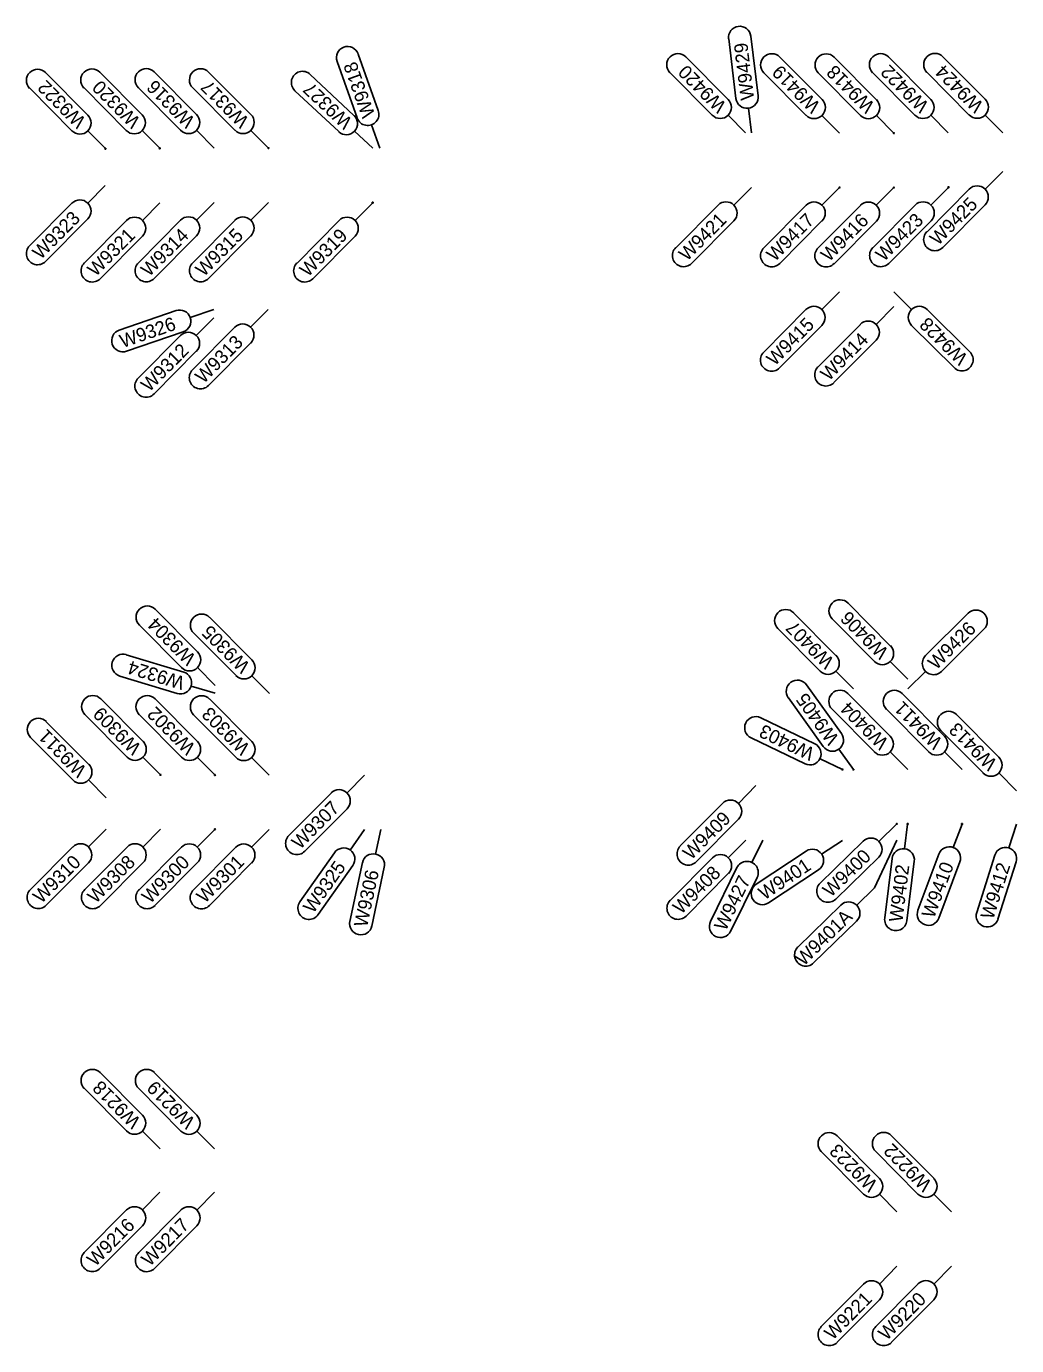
# Model space of a CAD drawing. Extents: x 12479652 to 12487250, y 9842710 to 9846560.
# Drawn here: x 12483660 to 12483751.1, y 9844143 to 9844264.3 of the extents above; entities that cross this region are included whole.
import ezdxf

# ---------------------------------------------------------------- set-up
doc = ezdxf.new("R2010")
doc.units = 0
for name, color, linetype in [('_CIVIL_CONSTRUCTION', 7, 'Continuous'), ('Default', 7, 'Continuous'), ('TextAlignmentLrg', 7, 'Continuous')]:
    doc.layers.add(name, color=color, linetype=linetype)

msp = doc.modelspace()

# ---------------------------------------------------------------- linework, layer by layer
at = {"layer": '_CIVIL_CONSTRUCTION'}
msp.add_line((12483738.04, 9844185.05), (12483740.08, 9844189.43), dxfattribs=at)
at = {"layer": 'Default'}
for p, q in [((12483724.62, 9844263.12), (12483725.29, 9844257.64)), ((12483727.33, 9844257.9), (12483726.65, 9844263.37)), ((12483692.39, 9844256.54), (12483690.53, 9844261.73)), ((12483724.56, 9844257.55), (12483720.67, 9844261.47)), ((12483733.21, 9844257.54), (12483729.32, 9844261.45)), ((12483738.21, 9844257.53), (12483734.32, 9844261.45)), ((12483743.21, 9844257.55), (12483739.32, 9844261.46)), ((12483748.21, 9844257.57), (12483744.32, 9844261.48)), ((12483665.68, 9844256.11), (12483661.79, 9844260.03)), ((12483670.68, 9844256.14), (12483666.79, 9844260.05)), ((12483675.68, 9844256.17), (12483671.79, 9844260.08)), ((12483680.68, 9844256.16), (12483676.79, 9844260.07)), ((12483690.16, 9844256.09), (12483686.14, 9844259.86)), ((12483688.6, 9844261.04), (12483690.46, 9844255.85)), ((12483719.22, 9844260.02), (12483723.11, 9844256.11)), ((12483727.86, 9844260.01), (12483731.75, 9844256.09)), ((12483732.86, 9844260), (12483736.75, 9844256.09)), ((12483737.86, 9844260.02), (12483741.75, 9844256.11)), ((12483742.86, 9844260.04), (12483746.75, 9844256.12)), ((12483660.34, 9844258.58), (12483664.22, 9844254.67)), ((12483665.34, 9844258.61), (12483669.22, 9844254.69)), ((12483670.34, 9844258.63), (12483674.22, 9844254.72)), ((12483675.34, 9844258.63), (12483679.22, 9844254.71)), ((12483684.73, 9844258.36), (12483688.76, 9844254.59)), ((12483726.72, 9844254.47), (12483726.44, 9844256.75)), ((12483692.54, 9844253.06), (12483691.77, 9844255.23)), ((12483726.18, 9844254.47), (12483724.56, 9844256.1)), ((12483734.82, 9844254.46), (12483733.2, 9844256.09)), ((12483739.82, 9844254.45), (12483738.2, 9844256.08)), ((12483744.82, 9844254.47), (12483743.2, 9844256.1)), ((12483749.82, 9844254.49), (12483748.2, 9844256.12)), ((12483667.3, 9844253.03), (12483665.68, 9844254.66)), ((12483672.3, 9844253.06), (12483670.68, 9844254.69)), ((12483677.3, 9844253.08), (12483675.68, 9844254.72)), ((12483682.3, 9844253.08), (12483680.68, 9844254.71)), ((12483691.89, 9844253.06), (12483690.21, 9844254.64)), ((12483749.82, 9844250.94), (12483748.2, 9844249.31)), ((12483667.29, 9844249.65), (12483665.67, 9844248.02)), ((12483726.71, 9844249.47), (12483725.09, 9844247.84)), ((12483734.82, 9844249.46), (12483733.19, 9844247.83)), ((12483739.82, 9844249.45), (12483738.19, 9844247.82)), ((12483742.86, 9844245.39), (12483746.75, 9844249.3)), ((12483744.84, 9844249.47), (12483743.22, 9844247.84)), ((12483660.33, 9844244.1), (12483664.22, 9844248.01)), ((12483672.32, 9844248.06), (12483670.7, 9844246.43)), ((12483677.29, 9844248.08), (12483675.67, 9844246.45)), ((12483682.29, 9844248.08), (12483680.67, 9844246.45)), ((12483691.88, 9844248.06), (12483690.26, 9844246.43)), ((12483719.75, 9844243.92), (12483723.64, 9844247.83)), ((12483727.85, 9844243.91), (12483731.74, 9844247.82)), ((12483732.85, 9844243.9), (12483736.74, 9844247.81)), ((12483737.88, 9844243.92), (12483741.77, 9844247.83)), ((12483748.2, 9844247.86), (12483744.31, 9844243.94)), ((12483665.67, 9844246.57), (12483661.79, 9844242.65)), ((12483665.36, 9844242.51), (12483669.25, 9844246.42)), ((12483670.33, 9844242.54), (12483674.22, 9844246.45)), ((12483675.33, 9844242.53), (12483679.22, 9844246.44)), ((12483684.92, 9844242.51), (12483688.81, 9844246.43)), ((12483725.1, 9844246.39), (12483721.21, 9844242.47)), ((12483733.2, 9844246.38), (12483729.31, 9844242.46)), ((12483738.2, 9844246.37), (12483734.31, 9844242.45)), ((12483743.23, 9844246.39), (12483739.34, 9844242.47)), ((12483670.71, 9844244.98), (12483666.82, 9844241.06)), ((12483675.67, 9844245), (12483671.78, 9844241.09)), ((12483680.67, 9844245), (12483676.78, 9844241.08)), ((12483690.26, 9844244.98), (12483686.37, 9844241.07)), ((12483734.8, 9844239.86), (12483733.18, 9844238.23)), ((12483739.8, 9844239.86), (12483741.43, 9844238.23)), ((12483668.58, 9844236.34), (12483673.8, 9844238.13)), ((12483677.27, 9844238.25), (12483675.1, 9844237.5)), ((12483682.27, 9844238.24), (12483680.65, 9844236.61)), ((12483727.84, 9844234.31), (12483731.73, 9844238.23)), ((12483739.8, 9844238.5), (12483738.18, 9844236.87)), ((12483742.88, 9844238.24), (12483746.8, 9844234.35)), ((12483677.27, 9844237.47), (12483675.65, 9844235.84)), ((12483732.84, 9844232.96), (12483736.73, 9844236.87)), ((12483674.46, 9844236.19), (12483669.25, 9844234.4)), ((12483670.31, 9844231.92), (12483674.2, 9844235.84)), ((12483675.31, 9844232.69), (12483679.2, 9844236.6)), ((12483733.18, 9844236.78), (12483729.29, 9844232.87)), ((12483745.35, 9844232.89), (12483741.44, 9844236.78)), ((12483675.66, 9844234.39), (12483671.77, 9844230.48)), ((12483680.66, 9844235.16), (12483676.77, 9844231.25)), ((12483738.18, 9844235.42), (12483734.29, 9844231.51)), ((12483675.77, 9844206.75), (12483671.88, 9844210.67)), ((12483734.48, 9844206.43), (12483730.59, 9844210.34)), ((12483739.48, 9844207.32), (12483735.6, 9844211.24)), ((12483746.65, 9844210.3), (12483742.73, 9844206.41)), ((12483670.42, 9844209.22), (12483674.31, 9844205.31)), ((12483680.77, 9844206.02), (12483676.88, 9844209.93)), ((12483734.14, 9844209.79), (12483738.03, 9844205.88)), ((12483675.42, 9844208.48), (12483679.31, 9844204.57)), ((12483729.14, 9844208.9), (12483733.03, 9844204.98)), ((12483744.18, 9844204.95), (12483748.09, 9844208.84)), ((12483674.5, 9844204.89), (12483669.22, 9844206.49)), ((12483677.39, 9844203.67), (12483675.76, 9844205.3)), ((12483741.1, 9844204.24), (12483739.48, 9844205.87)), ((12483668.63, 9844204.53), (12483673.9, 9844202.93)), ((12483682.38, 9844202.93), (12483680.76, 9844204.56)), ((12483736.1, 9844203.35), (12483734.48, 9844204.98)), ((12483741.1, 9844203.34), (12483742.73, 9844204.96)), ((12483677.38, 9844202.94), (12483675.18, 9844203.61)), ((12483734.99, 9844199.23), (12483731.78, 9844203.72)), ((12483739.47, 9844199.01), (12483735.58, 9844202.92)), ((12483744.47, 9844199), (12483740.58, 9844202.91)), ((12483670.76, 9844198.52), (12483666.87, 9844202.43)), ((12483675.76, 9844198.51), (12483671.87, 9844202.42)), ((12483680.76, 9844198.5), (12483676.87, 9844202.42)), ((12483730.11, 9844202.53), (12483733.32, 9844198.04)), ((12483665.41, 9844200.98), (12483669.3, 9844197.07)), ((12483670.41, 9844200.98), (12483674.3, 9844197.06)), ((12483675.41, 9844200.97), (12483679.3, 9844197.06)), ((12483732.54, 9844198.3), (12483727.57, 9844200.69)), ((12483734.13, 9844201.47), (12483738.02, 9844197.56)), ((12483739.13, 9844201.47), (12483743.02, 9844197.55)), ((12483749.47, 9844197.07), (12483745.58, 9844200.98)), ((12483665.75, 9844196.42), (12483661.86, 9844200.33)), ((12483744.12, 9844199.53), (12483748.01, 9844195.62)), ((12483660.41, 9844198.88), (12483664.3, 9844194.97)), ((12483726.68, 9844198.84), (12483731.65, 9844196.45)), ((12483672.37, 9844195.44), (12483670.75, 9844197.07)), ((12483677.37, 9844195.43), (12483675.75, 9844197.06)), ((12483682.37, 9844195.42), (12483680.75, 9844197.05)), ((12483735.09, 9844195.93), (12483733.02, 9844196.93)), ((12483736.09, 9844195.93), (12483734.75, 9844197.8)), ((12483741.09, 9844195.92), (12483739.47, 9844197.56)), ((12483746.09, 9844195.92), (12483744.47, 9844197.55)), ((12483751.09, 9844193.98), (12483749.46, 9844195.62)), ((12483667.37, 9844193.34), (12483665.75, 9844194.97)), ((12483691.14, 9844195.41), (12483689.52, 9844193.78)), ((12483727.13, 9844194.45), (12483725.51, 9844192.81)), ((12483684.18, 9844189.86), (12483688.07, 9844193.77)), ((12483689.52, 9844192.33), (12483685.63, 9844188.41)), ((12483720.17, 9844188.9), (12483724.06, 9844192.81)), ((12483725.51, 9844191.36), (12483721.63, 9844187.45)), ((12483740.08, 9844190.93), (12483738.43, 9844189.32)), ((12483741.08, 9844190.92), (12483740.8, 9844188.64)), ((12483746.08, 9844190.92), (12483745.28, 9844188.76)), ((12483751.08, 9844190.91), (12483750.39, 9844188.72)), ((12483667.37, 9844190.44), (12483665.74, 9844188.81)), ((12483672.37, 9844190.44), (12483670.74, 9844188.8)), ((12483677.37, 9844190.43), (12483675.74, 9844188.8)), ((12483682.37, 9844190.42), (12483680.74, 9844188.79)), ((12483691.13, 9844190.41), (12483689.8, 9844188.53)), ((12483692.64, 9844190.41), (12483692.15, 9844188.16)), ((12483660.4, 9844184.9), (12483664.29, 9844188.81)), ((12483665.4, 9844184.89), (12483669.29, 9844188.8)), ((12483670.4, 9844184.88), (12483674.29, 9844188.79)), ((12483675.4, 9844184.87), (12483679.29, 9844188.79)), ((12483685.19, 9844183.77), (12483688.37, 9844188.28)), ((12483726.2, 9844189.45), (12483724.58, 9844187.82)), ((12483727.77, 9844189.44), (12483726.76, 9844187.38)), ((12483727.16, 9844185.38), (12483731.75, 9844188.43)), ((12483733.03, 9844185.49), (12483736.98, 9844189.34)), ((12483735.09, 9844189.42), (12483733.17, 9844188.14)), ((12483665.75, 9844187.36), (12483661.86, 9844183.45)), ((12483670.75, 9844187.35), (12483666.86, 9844183.44)), ((12483675.75, 9844187.35), (12483671.86, 9844183.43)), ((12483680.75, 9844187.34), (12483676.86, 9844183.43)), ((12483690.05, 9844187.1), (12483686.87, 9844182.59)), ((12483689.78, 9844181.97), (12483690.94, 9844187.37)), ((12483719.24, 9844183.9), (12483723.13, 9844187.81)), ((12483738.42, 9844187.87), (12483734.46, 9844184.02)), ((12483738.97, 9844182.28), (12483739.65, 9844187.75)), ((12483741.69, 9844187.5), (12483741.01, 9844182.02)), ((12483742.03, 9844182.99), (12483743.96, 9844188.16)), ((12483745.88, 9844187.44), (12483743.95, 9844182.27)), ((12483747.43, 9844182.79), (12483749.1, 9844188.05)), ((12483751.05, 9844187.43), (12483749.38, 9844182.17)), ((12483692.94, 9844186.94), (12483691.79, 9844181.54)), ((12483724.58, 9844186.36), (12483720.7, 9844182.45)), ((12483722.95, 9844181.96), (12483725.38, 9844186.91)), ((12483727.23, 9844186.01), (12483724.79, 9844181.05)), ((12483732.89, 9844186.72), (12483728.29, 9844183.67)), ((12483738.04, 9844185.05), (12483736.39, 9844183.44)), ((12483730.99, 9844179.61), (12483734.94, 9844183.46)), ((12483736.37, 9844181.99), (12483732.42, 9844178.14)), ((12483670.71, 9844164.15), (12483666.82, 9844168.06)), ((12483675.71, 9844164.14), (12483671.82, 9844168.05)), ((12483665.37, 9844166.61), (12483669.25, 9844162.7)), ((12483670.37, 9844166.6), (12483674.25, 9844162.69)), ((12483672.33, 9844161.06), (12483670.71, 9844162.69)), ((12483677.33, 9844161.06), (12483675.71, 9844162.69)), ((12483738.48, 9844158.33), (12483734.6, 9844162.25)), ((12483743.48, 9844158.34), (12483739.6, 9844162.25)), ((12483733.14, 9844160.8), (12483737.03, 9844156.89)), ((12483738.14, 9844160.8), (12483742.03, 9844156.89)), ((12483672.32, 9844157.06), (12483670.7, 9844155.43)), ((12483677.32, 9844157.06), (12483675.7, 9844155.42)), ((12483740.1, 9844155.25), (12483738.48, 9844156.88)), ((12483745.1, 9844155.25), (12483743.48, 9844156.89)), ((12483665.36, 9844151.51), (12483669.25, 9844155.43)), ((12483670.36, 9844151.51), (12483674.25, 9844155.42)), ((12483670.7, 9844153.98), (12483666.81, 9844150.07)), ((12483675.7, 9844153.97), (12483671.81, 9844150.06)), ((12483740.1, 9844150.25), (12483738.48, 9844148.62)), ((12483745.1, 9844150.25), (12483743.48, 9844148.62)), ((12483733.14, 9844144.7), (12483737.03, 9844148.62)), ((12483738.14, 9844144.71), (12483742.03, 9844148.62)), ((12483738.49, 9844147.17), (12483734.6, 9844143.26)), ((12483743.49, 9844147.17), (12483739.6, 9844143.26))]:
    msp.add_line(p, q, dxfattribs=at)
for centre, start, end in [((12483725.63, 9844263.25), 7.0658, 187.0658), ((12483689.57, 9844261.39), 19.665, 199.665), ((12483719.95, 9844260.74), 44.8253, 224.8253), ((12483728.59, 9844260.73), 44.8253, 224.8253), ((12483733.59, 9844260.72), 44.8253, 224.8253), ((12483738.59, 9844260.74), 44.8253, 224.8253), ((12483743.59, 9844260.76), 44.8253, 224.8253), ((12483661.06, 9844259.3), 44.8253, 224.8253), ((12483666.06, 9844259.33), 44.8253, 224.8253), ((12483671.06, 9844259.36), 44.8253, 224.8253), ((12483676.06, 9844259.35), 44.8253, 224.8253), ((12483685.43, 9844259.11), 46.8471, 226.8471), ((12483723.84, 9844256.83), 224.8253, 44.8253), ((12483726.31, 9844257.77), 187.0658, 7.0658), ((12483732.48, 9844256.82), 224.8253, 44.8253), ((12483737.48, 9844256.81), 224.8253, 44.8253), ((12483742.48, 9844256.83), 224.8253, 44.8253), ((12483747.48, 9844256.85), 224.8253, 44.8253), ((12483691.42, 9844256.19), 199.665, 19.665), ((12483664.95, 9844255.39), 224.8253, 44.8253), ((12483669.95, 9844255.42), 224.8253, 44.8253), ((12483674.95, 9844255.44), 224.8253, 44.8253), ((12483679.95, 9844255.44), 224.8253, 44.8253), ((12483689.46, 9844255.34), 226.8471, 46.8471), ((12483747.47, 9844248.58), 315.1702, 135.1702), ((12483664.95, 9844247.29), 315.1702, 135.1702), ((12483724.37, 9844247.11), 315.1702, 135.1702), ((12483732.47, 9844247.1), 315.1702, 135.1702), ((12483737.47, 9844247.09), 315.1702, 135.1702), ((12483742.5, 9844247.11), 315.1702, 135.1702), ((12483669.98, 9844245.7), 315.1702, 135.1702), ((12483674.94, 9844245.73), 315.1702, 135.1702), ((12483679.94, 9844245.72), 315.1702, 135.1702), ((12483689.53, 9844245.7), 315.1702, 135.1702), ((12483743.58, 9844244.67), 135.1702, 315.1702), ((12483661.06, 9844243.38), 135.1702, 315.1702), ((12483720.48, 9844243.2), 135.1702, 315.1702), ((12483728.58, 9844243.19), 135.1702, 315.1702), ((12483733.58, 9844243.18), 135.1702, 315.1702), ((12483738.61, 9844243.2), 135.1702, 315.1702), ((12483666.09, 9844241.79), 135.1702, 315.1702), ((12483671.06, 9844241.81), 135.1702, 315.1702), ((12483676.06, 9844241.81), 135.1702, 315.1702), ((12483685.64, 9844241.79), 135.1702, 315.1702), ((12483674.13, 9844237.16), 289.0233, 109.0233), ((12483732.46, 9844237.5), 315.1702, 135.1702), ((12483742.16, 9844237.51), 45.1702, 225.1702), ((12483679.93, 9844235.88), 315.1702, 135.1702), ((12483737.45, 9844236.14), 315.1702, 135.1702), ((12483668.91, 9844235.37), 109.0233, 289.0233), ((12483674.93, 9844235.11), 315.1702, 135.1702), ((12483728.57, 9844233.59), 135.1702, 315.1702), ((12483746.07, 9844233.62), 225.1702, 45.1702), ((12483676.04, 9844231.97), 135.1702, 315.1702), ((12483733.56, 9844232.23), 135.1702, 315.1702), ((12483671.04, 9844231.2), 135.1702, 315.1702), ((12483734.87, 9844210.51), 44.8253, 224.8253), ((12483671.15, 9844209.94), 44.8253, 224.8253), ((12483676.15, 9844209.2), 44.8253, 224.8253), ((12483729.87, 9844209.62), 44.8253, 224.8253), ((12483747.37, 9844209.57), 314.8253, 134.8253), ((12483668.92, 9844205.51), 73.1071, 253.1071), ((12483675.04, 9844206.03), 224.8253, 44.8253), ((12483738.76, 9844206.6), 224.8253, 44.8253), ((12483680.04, 9844205.29), 224.8253, 44.8253), ((12483733.76, 9844205.71), 224.8253, 44.8253), ((12483743.46, 9844205.68), 134.8253, 314.8253), ((12483674.2, 9844203.91), 253.1071, 73.1071), ((12483730.94, 9844203.12), 35.5978, 215.5978), ((12483734.86, 9844202.2), 44.8253, 224.8253), ((12483739.86, 9844202.19), 44.8253, 224.8253), ((12483666.14, 9844201.71), 44.8253, 224.8253), ((12483671.14, 9844201.7), 44.8253, 224.8253), ((12483676.14, 9844201.69), 44.8253, 224.8253), ((12483661.14, 9844199.61), 44.8253, 224.8253), ((12483727.12, 9844199.77), 64.3063, 244.3063), ((12483744.85, 9844200.26), 44.8253, 224.8253), ((12483734.15, 9844198.64), 215.5978, 35.5978), ((12483670.03, 9844197.8), 224.8253, 44.8253), ((12483675.03, 9844197.79), 224.8253, 44.8253), ((12483680.03, 9844197.78), 224.8253, 44.8253), ((12483732.09, 9844197.38), 244.3063, 64.3063), ((12483738.74, 9844198.28), 224.8253, 44.8253), ((12483743.74, 9844198.28), 224.8253, 44.8253), ((12483748.74, 9844196.34), 224.8253, 44.8253), ((12483665.03, 9844195.7), 224.8253, 44.8253), ((12483688.79, 9844193.05), 315.1702, 135.1702), ((12483724.79, 9844192.09), 315.1702, 135.1702), ((12483684.9, 9844189.14), 135.1702, 315.1702), ((12483737.7, 9844188.6), 314.2533, 134.2533), ((12483665.02, 9844188.08), 315.1702, 135.1702), ((12483670.02, 9844188.08), 315.1702, 135.1702), ((12483675.02, 9844188.07), 315.1702, 135.1702), ((12483680.02, 9844188.06), 315.1702, 135.1702), ((12483689.21, 9844187.69), 324.788, 144.788), ((12483720.9, 9844188.17), 135.1702, 315.1702), ((12483732.32, 9844187.58), 303.5694, 123.5694), ((12483740.67, 9844187.62), 352.9021, 172.9021), ((12483744.92, 9844187.8), 339.5552, 159.5552), ((12483750.08, 9844187.74), 342.3954, 162.3954), ((12483691.94, 9844187.15), 347.9405, 167.9405), ((12483723.86, 9844187.09), 315.1702, 135.1702), ((12483726.31, 9844186.46), 333.8437, 153.8437), ((12483661.13, 9844184.17), 135.1702, 315.1702), ((12483666.13, 9844184.16), 135.1702, 315.1702), ((12483671.13, 9844184.16), 135.1702, 315.1702), ((12483676.13, 9844184.15), 135.1702, 315.1702), ((12483727.72, 9844184.53), 123.5694, 303.5694), ((12483733.75, 9844184.75), 134.2533, 314.2533), ((12483686.03, 9844183.18), 144.788, 324.788), ((12483719.97, 9844183.18), 135.1702, 315.1702), ((12483735.66, 9844182.73), 314.2533, 134.2533), ((12483739.99, 9844182.15), 172.9021, 352.9021), ((12483742.99, 9844182.63), 159.5552, 339.5552), ((12483748.41, 9844182.48), 162.3954, 342.3954), ((12483690.79, 9844181.76), 167.9405, 347.9405), ((12483723.87, 9844181.51), 153.8437, 333.8437), ((12483731.71, 9844178.88), 134.2533, 314.2533), ((12483666.09, 9844167.33), 44.8253, 224.8253), ((12483671.09, 9844167.33), 44.8253, 224.8253), ((12483669.98, 9844163.42), 224.8253, 44.8253), ((12483674.98, 9844163.41), 224.8253, 44.8253), ((12483733.87, 9844161.52), 44.8253, 224.8253), ((12483738.87, 9844161.53), 44.8253, 224.8253), ((12483737.76, 9844157.61), 224.8253, 44.8253), ((12483742.76, 9844157.61), 224.8253, 44.8253), ((12483669.98, 9844154.7), 315.1702, 135.1702), ((12483674.98, 9844154.7), 315.1702, 135.1702), ((12483666.09, 9844150.79), 135.1702, 315.1702), ((12483671.09, 9844150.78), 135.1702, 315.1702), ((12483737.76, 9844147.89), 315.1702, 135.1702), ((12483742.76, 9844147.9), 315.1702, 135.1702), ((12483733.87, 9844143.98), 135.1702, 315.1702), ((12483738.87, 9844143.98), 135.1702, 315.1702)]:
    msp.add_arc(centre, 1.03, start, end, dxfattribs=at)
at = {"layer": 'TextAlignmentLrg'}
for centre in [(12483739.82, 9844254.45), (12483667.3, 9844253.03), (12483672.3, 9844253.06), (12483682.3, 9844253.08), (12483734.82, 9844249.46), (12483739.82, 9844249.45), (12483744.84, 9844249.47), (12483691.88, 9844248.06), (12483735.09, 9844195.93), (12483736.09, 9844195.93), (12483672.37, 9844195.44), (12483677.37, 9844195.43), (12483740.08, 9844190.93), (12483741.08, 9844190.92), (12483746.08, 9844190.92), (12483677.37, 9844190.43)]:
    msp.add_circle(centre, 0.05, dxfattribs=at)

# ---------------------------------------------------------------- texts
at = {"layer": 'Default'}
for s, rotation, p in [('W9429', 97.0658, (12483726.98, 9844257.57)), ('W9318', 109.665, (12483692.12, 9844256.14)), ('W9420', 134.8253, (12483724.49, 9844257.07)), ('W9419', 134.8253, (12483733.13, 9844257.06)), ('W9418', 134.8253, (12483738.13, 9844257.06)), ('W9422', 134.8253, (12483743.11, 9844257.09)), ('W9424', 134.8253, (12483748.14, 9844257.09)), ('W9322', 134.8253, (12483665.58, 9844255.66)), ('W9320', 134.8253, (12483670.6, 9844255.66)), ('W9316', 134.8253, (12483675.61, 9844255.69)), ('W9317', 134.8253, (12483680.59, 9844255.69)), ('W9327', 136.8471, (12483690.09, 9844255.62)), ('W9425', 45.1702, (12483743.87, 9844244.05)), ('W9323', 45.1702, (12483661.34, 9844242.76)), ('W9421', 45.1702, (12483720.79, 9844242.61)), ('W9417', 45.1702, (12483728.86, 9844242.57)), ('W9416', 45.1702, (12483733.85, 9844242.55)), ('W9423', 45.1702, (12483738.89, 9844242.58)), ('W9321', 45.1702, (12483666.4, 9844241.19)), ('W9314', 45.1702, (12483671.32, 9844241.18)), ('W9315', 45.1702, (12483676.34, 9844241.19)), ('W9319', 45.1702, (12483685.92, 9844241.16)), ('W9326', 19.0233, (12483668.88, 9844234.68)), ('W9415', 45.1702, (12483728.85, 9844232.98)), ('W9428', 135.1702, (12483746.7, 9844233.89)), ('W9313', 45.1702, (12483676.32, 9844231.35)), ('W9414', 45.1702, (12483733.83, 9844231.6)), ('W9312', 45.1702, (12483671.33, 9844230.59)), ('W9406', 134.8253, (12483739.41, 9844206.84)), ('W9304', 134.8253, (12483675.7, 9844206.27)), ('W9305', 134.8253, (12483680.68, 9844205.55)), ('W9407', 134.8253, (12483734.4, 9844205.96)), ('W9426', 44.8253, (12483743.7, 9844205.03)), ('W9324', 163.1071, (12483674.67, 9844204.43)), ('W9405', 125.5978, (12483734.83, 9844198.79)), ('W9302', 134.8253, (12483675.66, 9844198.05)), ('W9404', 134.8253, (12483739.4, 9844198.52)), ('W9411', 134.8253, (12483744.36, 9844198.56)), ('W9309', 134.8253, (12483670.68, 9844198.04)), ('W9303', 134.8253, (12483680.67, 9844198.03)), ('W9311', 134.8253, (12483665.64, 9844195.98)), ('W9403', 154.3063, (12483732.61, 9844197.83)), ('W9413', 134.8253, (12483749.39, 9844196.6)), ('W9307', 45.1702, (12483685.19, 9844188.52)), ('W9409', 45.1702, (12483721.17, 9844187.55)), ('W9400', 44.2533, (12483734.01, 9844184.12)), ('W9310', 45.1702, (12483661.4, 9844183.54)), ('W9308', 45.1702, (12483666.4, 9844183.54)), ('W9300', 45.1702, (12483671.4, 9844183.53)), ('W9301', 45.1702, (12483676.44, 9844183.56)), ('W9325', 54.788, (12483686.41, 9844182.62)), ('W9401', 33.5694, (12483727.9, 9844183.88)), ('W9402', 82.9021, (12483740.59, 9844181.85)), ('W9410', 69.5552, (12483743.5, 9844182.17)), ('W9412', 72.3954, (12483748.94, 9844182.07)), ('W9306', 77.9405, (12483691.36, 9844181.37)), ('W9408', 45.1702, (12483720.24, 9844182.55)), ('W9427', 63.8437, (12483724.34, 9844181.01)), ('W9401A', 44.2533, (12483731.51, 9844177.8)), ('W9218', 134.8253, (12483670.63, 9844163.67)), ('W9219', 134.8253, (12483675.63, 9844163.66)), ('W9223', 134.8253, (12483738.4, 9844157.86)), ('W9222', 134.8253, (12483743.39, 9844157.88)), ('W9216', 45.1702, (12483666.36, 9844150.16)), ('W9217', 45.1702, (12483671.37, 9844150.17)), ('W9221', 45.1702, (12483734.18, 9844143.39)), ('W9220', 45.1702, (12483739.14, 9844143.35))]:
    msp.add_text(s, height=1.25, rotation=rotation, dxfattribs=at).set_placement(p)

doc.saveas('drawing.dxf')
